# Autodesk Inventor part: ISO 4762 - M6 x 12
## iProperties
Comments: To add or edit properties for Autodesk Inventor files, use iProperties.
Created: 2004-04
Part Number: ISO 4762 - M6 x 12
Vendor: Autodesk Inc.
Document SubType Name: Modeling
Designer: rak
Material: Default
Description: Hexagon Socket Head Cap Screw
Standard: ISO 4762
Size Designation: M6 x 12
Alert: To add or edit properties for Autodesk Inventor files, use iProperties.
Control State: 0
Master: False
Checked Out: False
Shininess: 64.0
Length Units: 11269
Angle Units: 11279
Time Units: 11290
Mass Units: 11283
Length Display Precision: 3
Angle Display Precision: 2
Compacted: True
EGR: 1
Density: 0.0
Volumn: 0.0
Area: 0.0
PropertySet Name: Model Information
Author: rak
Revision Number: 8
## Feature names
1. Body [Revolution]
2. Slot [Extrusion]
3. Fillet1
4. Chamfer1
